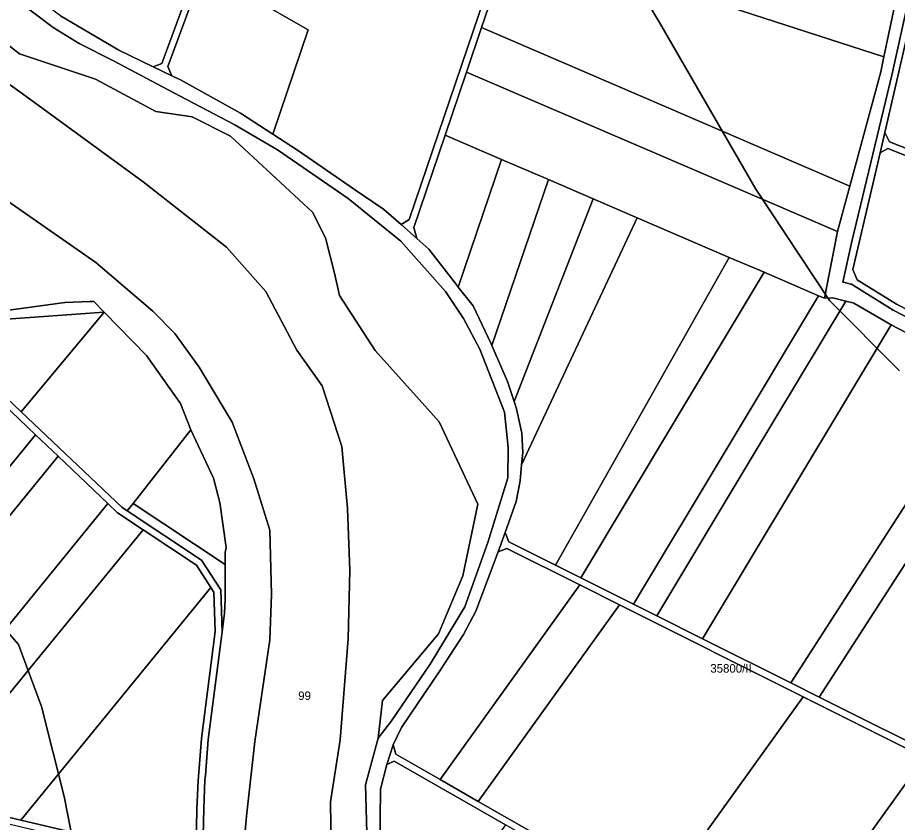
# Model space of a CAD drawing. Extents: x -545779 to -541342, y -1153413 to -1149956.
# Drawn here: x -542843 to -542328, y -1151005 to -1150533 of the extents above; entities that cross this region are included whole.
import ezdxf

# ---------------------------------------------------------------- set-up
doc = ezdxf.new("R2010")
doc.units = 0
for name, color, linetype in [('95560013', 7, 'Continuous'), ('95610013', 7, 'Continuous'), ('95620013', 7, 'Continuous'), ('95630013', 7, 'Continuous'), ('95640013', 7, 'Continuous'), ('95660013', 7, 'Continuous')]:
    doc.layers.add(name, color=color, linetype=linetype)

msp = doc.modelspace()

# ---------------------------------------------------------------- linework, layer by layer
at = {"layer": '95560013'}
for points in [[(-542330.19, -1150487.71), (-542329.65, -1150527.02), (-542335.84, -1150556.5), (-542444.5, -1150521.18), (-542553.15, -1150485.85), (-542525.28, -1150403.7), (-542332.68, -1150445.62)], [(-542645.66, -1150634.13), (-542678.6, -1150611.44), (-542693.55, -1150601.76), (-542672.83, -1150540.72), (-542734.13, -1150505.55), (-542702.1, -1150418.51), (-542538.9, -1150431.11), (-542576.35, -1150541.42), (-542613.8, -1150651.74), (-542618.41, -1150654.69), (-542628.79, -1150645.63)], [(-542763.51, -1150562.3), (-542783.62, -1150552.52), (-542817.82, -1150532.5), (-542849.86, -1150508.94), (-542861.66, -1150502.34), (-542839.07, -1150445.37), (-542737.65, -1150503.54), (-542758.53, -1150560.29)], [(-542337.68, -1150565.29), (-542355.74, -1150632.12), (-542463.52, -1150585.76), (-542571.31, -1150539.39), (-542553.15, -1150485.85), (-542444.5, -1150521.18), (-542335.84, -1150556.5)], [(-542238.79, -1150518.76), (-542265.23, -1150632.79), (-542332.56, -1150606.25), (-542335.38, -1150600.88), (-542318.46, -1150527.93), (-542319.28, -1150493.32)], [(-542747.63, -1150570.02), (-542752.7, -1150567.55), (-542754.92, -1150562.05), (-542734.13, -1150505.55), (-542672.83, -1150540.72), (-542693.55, -1150601.76), (-542712.51, -1150589.48)], [(-542471.54, -1150612.08), (-542580.12, -1150565.37), (-542571.31, -1150539.39), (-542463.52, -1150585.76), (-542355.74, -1150632.12), (-542362.95, -1150658.79)], [(-542580.12, -1150565.37), (-542471.54, -1150612.08), (-542362.95, -1150658.79), (-542363.21, -1150659.75), (-542370.7, -1150697.82), (-542374.07, -1150696.37), (-542405.95, -1150682.66), (-542426.33, -1150673.89), (-542480.19, -1150650.72), (-542505.95, -1150639.64), (-542532.27, -1150628.32), (-542559.66, -1150616.54), (-542592.68, -1150602.33)], [(-542586.51, -1150689.38), (-542602.24, -1150669.02), (-542609.26, -1150662.77), (-542610.97, -1150656.32), (-542592.68, -1150602.33), (-542559.66, -1150616.54), (-542585.01, -1150691.28)], [(-542303.72, -1150714.04), (-542305.3, -1150713.22), (-542328.41, -1150701.27), (-542351.47, -1150687.05), (-542353.96, -1150681.05), (-542338.1, -1150612.62), (-542333.47, -1150610.19), (-542284.15, -1150629.63)], [(-542532.27, -1150628.32), (-542565.25, -1150725.57), (-542565.68, -1150724.59), (-542576.23, -1150702.32), (-542585.01, -1150691.28), (-542559.66, -1150616.54)], [(-542505.95, -1150639.64), (-542552.24, -1150758.4), (-542556.14, -1150746.63), (-542565.25, -1150725.57), (-542532.27, -1150628.32)], [(-542547.18, -1150788.22), (-542547.73, -1150776.78), (-542550.87, -1150762.55), (-542552.24, -1150758.4), (-542505.95, -1150639.64), (-542480.19, -1150650.72), (-542547.89, -1150795.48)], [(-542551.16, -1150816.8), (-542548.81, -1150804.8), (-542547.89, -1150795.48), (-542480.19, -1150650.72), (-542426.33, -1150673.89), (-542477.22, -1150764.01), (-542528.11, -1150854.13), (-542555.31, -1150840.52), (-542557.56, -1150834.96)], [(-542426.33, -1150673.89), (-542405.95, -1150682.66), (-542459.52, -1150771.94), (-542513.29, -1150861.55), (-542528.11, -1150854.13), (-542477.22, -1150764.01)], [(-542428.26, -1150786.68), (-542482.44, -1150876.98), (-542513.29, -1150861.55), (-542459.52, -1150771.94), (-542405.95, -1150682.66), (-542374.07, -1150696.37)], [(-542374.07, -1150696.37), (-542370.7, -1150697.82), (-542365.74, -1150697.59), (-542358.22, -1150699.49), (-542413.51, -1150791.64), (-542468.81, -1150883.8), (-542482.44, -1150876.98), (-542428.26, -1150786.68)], [(-542413.51, -1150791.64), (-542358.22, -1150699.49), (-542354, -1150700.56), (-542353.42, -1150700.71), (-542331.67, -1150713.45), (-542386.81, -1150805.35), (-542441.95, -1150897.24), (-542468.81, -1150883.8)], [(-542274.43, -1150743.21), (-542332.4, -1150833.13), (-542390.37, -1150923.05), (-542441.95, -1150897.24), (-542386.81, -1150805.35), (-542331.67, -1150713.45)], [(-542332.4, -1150833.13), (-542274.43, -1150743.21), (-542257.9, -1150751.81), (-542315.79, -1150841.6), (-542373.68, -1150931.4), (-542390.37, -1150923.05)], [(-542257.9, -1150751.81), (-542196.89, -1150783.53), (-542172.78, -1150796.01), (-542235.1, -1150882.79), (-542297.41, -1150969.57), (-542373.68, -1150931.4), (-542315.79, -1150841.6)], [(-542856.45, -1150755.01), (-542832.51, -1150777.76), (-542910.52, -1150873.23), (-542988.53, -1150968.7), (-543024.19, -1150960.3), (-542940.33, -1150857.67)], [(-542819.24, -1150790.38), (-542894, -1150881.87), (-542968.76, -1150973.35), (-542988.53, -1150968.7), (-542910.52, -1150873.23), (-542832.51, -1150777.76)], [(-542925.32, -1150983.58), (-542968.76, -1150973.35), (-542894, -1150881.87), (-542819.24, -1150790.38), (-542790.1, -1150818.09), (-542857.71, -1150900.84)], [(-542784.49, -1150823.42), (-542769.44, -1150833.43), (-542833.46, -1150911.78), (-542897.48, -1150990.13), (-542925.32, -1150983.58), (-542857.71, -1150900.84), (-542790.1, -1150818.09)], [(-542729.75, -1150867.3), (-542840.99, -1151003.43), (-542897.48, -1150990.13), (-542833.46, -1150911.78), (-542769.44, -1150833.43), (-542738.27, -1150854.18)], [(-542595.71, -1150916.11), (-542581.96, -1150894.8), (-542574.79, -1150881.02), (-542561.62, -1150846.28), (-542556.63, -1150844.33), (-542513.84, -1150865.74), (-542595.66, -1150979.67), (-542621.45, -1150964.92), (-542623.17, -1150959.34), (-542618.19, -1150949.13)], [(-542595.66, -1150979.67), (-542513.84, -1150865.74), (-542490.6, -1150877.37), (-542573.26, -1150992.48)], [(-542729.75, -1150867.3), (-542728.03, -1150869.94), (-542727.2, -1150893.07), (-542735.35, -1150955.74), (-542737.3, -1150980.51), (-542737.99, -1150996.76), (-542738.48, -1151020.04), (-542738.32, -1151027.6), (-542840.99, -1151003.43)], [(-542383.03, -1150931.2), (-542312.07, -1150966.7), (-542401.24, -1151090.85), (-542469.6, -1151051.76)], [(-542623.4, -1151098.08), (-542630.67, -1151064.57), (-542630.81, -1151049.59), (-542629.35, -1151044.93), (-542629.55, -1151024.45), (-542630.99, -1151020.31), (-542630.5, -1150985.34), (-542626.89, -1150970.85), (-542622.45, -1150968.96), (-542557.39, -1151006.17)], [(-542401.24, -1151090.85), (-542312.07, -1150966.7), (-542234.43, -1151005.56), (-542326.42, -1151133.64)]]:
    msp.add_lwpolyline(points, close=True, dxfattribs=at)
at = {"layer": '95610013'}
for points in [[(-542852.21, -1150710.28), (-542792.22, -1150705.95), (-542840.86, -1150764.31), (-542879.48, -1150727.6), (-542863.52, -1150707.95)], [(-542792.22, -1150705.95), (-542767.48, -1150731.43), (-542747.62, -1150759.55), (-542741.51, -1150774.97), (-542775.27, -1150817.95), (-542778.77, -1150822.41), (-542781.98, -1150820.28), (-542840.86, -1150764.31)], [(-542573.26, -1150992.48), (-542490.6, -1150877.37), (-542383.03, -1150931.2), (-542469.6, -1151051.76)]]:
    msp.add_lwpolyline(points, close=True, dxfattribs=at)
at = {"layer": '95620013'}
for points in [[(-542724.58, -1150817.54), (-542720.95, -1150843.81), (-542721.4, -1150846.72), (-542721.41, -1150853.81), (-542775.27, -1150817.95), (-542741.51, -1150774.97), (-542732.72, -1150793.68), (-542728.24, -1150803.21)], [(-542778.77, -1150822.41), (-542775.27, -1150817.95), (-542721.41, -1150853.81), (-542721.43, -1150860.66), (-542721.46, -1150874.27), (-542721.75, -1150882.21), (-542723.19, -1150893.25), (-542724.07, -1150868.69), (-542735.37, -1150851.31)]]:
    msp.add_lwpolyline(points, close=True, dxfattribs=at)
at = {"layer": '95630013'}
for points in [[(-542274.43, -1150743.21), (-542331.67, -1150713.45), (-542353.42, -1150700.71), (-542354, -1150700.56), (-542358.22, -1150699.49), (-542365.74, -1150697.59), (-542370.7, -1150697.82), (-542363.21, -1150659.75), (-542362.95, -1150658.79), (-542355.74, -1150632.12), (-542337.68, -1150565.29), (-542335.84, -1150556.5), (-542329.65, -1150527.02)], [(-542322.47, -1150527.52), (-542331.21, -1150567.12), (-542354.69, -1150664.61), (-542359.8, -1150688.41), (-542359.5, -1150688.49), (-542355.18, -1150689.58), (-542354.84, -1150689.67), (-542330.38, -1150704.75), (-542192.55, -1150776.06)], [(-542853.27, -1150568.8), (-542840.3, -1150577.96), (-542769.53, -1150629.69), (-542720.62, -1150667.89), (-542697.73, -1150693.85), (-542679.4, -1150728.18), (-542664.57, -1150749.17), (-542653.18, -1150784.63), (-542649.87, -1150820.92), (-542648.38, -1150857.27), (-542649.36, -1150897.36), (-542654.05, -1150956.36), (-542659.77, -1150992.79), (-542659.3, -1151020.78)], [(-542711.12, -1151025.21), (-542708.98, -1151001.05), (-542704.01, -1150957.37), (-542695.25, -1150897.83), (-542694.4, -1150871.37), (-542695.3, -1150833.71), (-542704.75, -1150803.6), (-542717.27, -1150770.47), (-542736.65, -1150738.22), (-542750.99, -1150718.53), (-542763.83, -1150705.4), (-542797.14, -1150676.99), (-542877.1, -1150621.25)]]:
    msp.add_lwpolyline(points, dxfattribs=at)
at = {"layer": '95640013'}
msp.add_lwpolyline([(-542680.59, -1150348.45), (-542673.59, -1150329.44), (-542612.5, -1150163.4), (-542614.98, -1150158.86), (-542611.81, -1150160.9), (-542604.8, -1150165.43), (-542610.13, -1150168.54), (-542617.93, -1150189.75), (-542642.91, -1150257.63), (-542651.79, -1150281.78), (-542662.14, -1150309.9), (-542673.7, -1150341.32), (-542678.36, -1150353.99), (-542695.93, -1150401.74), (-542702.1, -1150418.51), (-542734.13, -1150505.55), (-542754.92, -1150562.05), (-542752.7, -1150567.55), (-542763.51, -1150562.3), (-542758.53, -1150560.29), (-542737.65, -1150503.54), (-542722.86, -1150463.35), (-542698.75, -1150397.83)], close=True, dxfattribs=at)
for points in [[(-542553.15, -1150485.85), (-542571.31, -1150539.39), (-542580.12, -1150565.37), (-542592.68, -1150602.33), (-542610.97, -1150656.32), (-542609.26, -1150662.77), (-542618.41, -1150654.69), (-542613.8, -1150651.74), (-542576.35, -1150541.42), (-542538.9, -1150431.11)], [(-542854.19, -1150515.06), (-542822.11, -1150539.26), (-542806.95, -1150548.7), (-542786.83, -1150558.73), (-542751.54, -1150577.56), (-542716.17, -1150596.02), (-542690.78, -1150610.95), (-542649.47, -1150639.4), (-542618.67, -1150664.43), (-542592.51, -1150693.89), (-542581.97, -1150709.69), (-542572.32, -1150727.63), (-542558.01, -1150764.47), (-542555.82, -1150785.27), (-542555.97, -1150802.94), (-542567.63, -1150840.97), (-542581.09, -1150878.47), (-542601.49, -1150912.16), (-542624.02, -1150945.26), (-542631.93, -1150955.49), (-542629.3, -1150933.48), (-542596.64, -1150894.43), (-542582.38, -1150860.37), (-542573.58, -1150818.49), (-542596.15, -1150770.14), (-542607.9, -1150757.1), (-542633.68, -1150728.52), (-542654.53, -1150696.16), (-542657.39, -1150683.24), (-542662.72, -1150662.44), (-542670.37, -1150647.36), (-542718.31, -1150602.84), (-542740.68, -1150591.53), (-542762.06, -1150588.54), (-542797.36, -1150569.62), (-542841.86, -1150554.66), (-542931.65, -1150484.68)], [(-542931.65, -1150484.68), (-542841.86, -1150554.66), (-542797.36, -1150569.62), (-542762.06, -1150588.54), (-542740.68, -1150591.53), (-542718.31, -1150602.84), (-542670.37, -1150647.36), (-542662.72, -1150662.44), (-542657.39, -1150683.24), (-542654.53, -1150696.16), (-542633.68, -1150728.52), (-542607.9, -1150757.1), (-542596.15, -1150770.14), (-542573.58, -1150818.49), (-542582.38, -1150860.37), (-542596.64, -1150894.43), (-542629.3, -1150933.48), (-542631.93, -1150955.49), (-542639.22, -1150982.71), (-542638.05, -1151024.8)], [(-542638.05, -1151024.8), (-542639.22, -1150982.71), (-542631.93, -1150955.49), (-542624.02, -1150945.26), (-542601.49, -1150912.16), (-542581.09, -1150878.47), (-542567.63, -1150840.97), (-542555.97, -1150802.94), (-542555.82, -1150785.27), (-542558.01, -1150764.47), (-542572.32, -1150727.63), (-542581.97, -1150709.69), (-542592.51, -1150693.89), (-542618.67, -1150664.43), (-542649.47, -1150639.4), (-542690.78, -1150610.95), (-542716.17, -1150596.02), (-542751.54, -1150577.56), (-542786.83, -1150558.73), (-542806.95, -1150548.7), (-542822.11, -1150539.26), (-542854.19, -1150515.06)], [(-542192.55, -1150776.06), (-542330.38, -1150704.75), (-542354.84, -1150689.67), (-542355.18, -1150689.58), (-542359.5, -1150688.49), (-542359.8, -1150688.41), (-542354.69, -1150664.61), (-542331.21, -1150567.12), (-542322.47, -1150527.52)], [(-542318.46, -1150527.93), (-542335.38, -1150600.88), (-542338.1, -1150612.62), (-542353.96, -1150681.05), (-542351.47, -1150687.05), (-542328.41, -1150701.27), (-542305.3, -1150713.22)], [(-542817.82, -1150532.5), (-542783.62, -1150552.52), (-542763.51, -1150562.3), (-542752.7, -1150567.55), (-542747.63, -1150570.02), (-542712.51, -1150589.48), (-542693.55, -1150601.76), (-542678.6, -1150611.44), (-542645.66, -1150634.13), (-542628.79, -1150645.63), (-542618.41, -1150654.69), (-542609.26, -1150662.77), (-542602.24, -1150669.02), (-542586.51, -1150689.38), (-542585.01, -1150691.28), (-542576.23, -1150702.32), (-542565.68, -1150724.59), (-542565.25, -1150725.57), (-542556.14, -1150746.63), (-542552.24, -1150758.4), (-542550.87, -1150762.55), (-542547.73, -1150776.78), (-542547.18, -1150788.22), (-542547.89, -1150795.48), (-542548.81, -1150804.8), (-542551.16, -1150816.8), (-542557.56, -1150834.96), (-542561.62, -1150846.28), (-542574.79, -1150881.02), (-542581.96, -1150894.8), (-542595.71, -1150916.11), (-542618.19, -1150949.13), (-542623.17, -1150959.34), (-542626.89, -1150970.85), (-542630.5, -1150985.34), (-542630.99, -1151020.31)], [(-542659.3, -1151020.78), (-542659.77, -1150992.79), (-542654.05, -1150956.36), (-542649.36, -1150897.36), (-542648.38, -1150857.27), (-542649.87, -1150820.92), (-542653.18, -1150784.63), (-542664.57, -1150749.17), (-542679.4, -1150728.18), (-542697.73, -1150693.85), (-542720.62, -1150667.89), (-542769.53, -1150629.69), (-542840.3, -1150577.96), (-542853.27, -1150568.8)], [(-542284.15, -1150629.63), (-542333.47, -1150610.19), (-542338.1, -1150612.62), (-542335.38, -1150600.88), (-542332.56, -1150606.25), (-542265.23, -1150632.79)], [(-542877.1, -1150621.25), (-542797.14, -1150676.99), (-542763.83, -1150705.4), (-542750.99, -1150718.53), (-542736.65, -1150738.22), (-542717.27, -1150770.47), (-542704.75, -1150803.6), (-542695.3, -1150833.71), (-542694.4, -1150871.37), (-542695.25, -1150897.83), (-542704.01, -1150957.37), (-542708.98, -1151001.05), (-542711.12, -1151025.21)], [(-542734.48, -1151020.04), (-542733.99, -1150996.89), (-542733.27, -1150979.77), (-542733.04, -1150977.32), (-542731.37, -1150956.16), (-542723.19, -1150893.25), (-542721.75, -1150882.21), (-542721.46, -1150874.27), (-542721.43, -1150860.66), (-542721.41, -1150853.81), (-542721.4, -1150846.72), (-542720.95, -1150843.81), (-542724.58, -1150817.54), (-542728.24, -1150803.21), (-542732.72, -1150793.68), (-542741.51, -1150774.97), (-542747.62, -1150759.55), (-542767.48, -1150731.43), (-542792.22, -1150705.95), (-542798.33, -1150699.67), (-542800.68, -1150699.77), (-542815.36, -1150700.43), (-542839.4, -1150703.66), (-542852.6, -1150705.43)], [(-542852.6, -1150705.43), (-542839.4, -1150703.66), (-542815.36, -1150700.43), (-542800.68, -1150699.77), (-542798.33, -1150699.67), (-542792.22, -1150705.95), (-542852.21, -1150710.28)], [(-542879.48, -1150727.6), (-542840.86, -1150764.31), (-542781.98, -1150820.28), (-542778.77, -1150822.41), (-542735.37, -1150851.31), (-542724.07, -1150868.69), (-542723.19, -1150893.25), (-542731.37, -1150956.16), (-542733.04, -1150977.32), (-542733.27, -1150979.77), (-542733.99, -1150996.89), (-542734.48, -1151020.04)], [(-542738.48, -1151020.04), (-542737.99, -1150996.76), (-542737.3, -1150980.51), (-542735.35, -1150955.74), (-542727.2, -1150893.07), (-542728.03, -1150869.94), (-542729.75, -1150867.3), (-542738.27, -1150854.18), (-542769.44, -1150833.43), (-542784.49, -1150823.42), (-542790.1, -1150818.09), (-542819.24, -1150790.38), (-542832.51, -1150777.76), (-542856.45, -1150755.01)], [(-542312.07, -1150966.7), (-542383.03, -1150931.2), (-542490.6, -1150877.37), (-542513.84, -1150865.74), (-542556.63, -1150844.33), (-542561.62, -1150846.28), (-542557.56, -1150834.96), (-542555.31, -1150840.52), (-542528.11, -1150854.13), (-542513.29, -1150861.55), (-542482.44, -1150876.98), (-542468.81, -1150883.8), (-542441.95, -1150897.24), (-542390.37, -1150923.05), (-542373.68, -1150931.4), (-542297.41, -1150969.57)], [(-542295.47, -1151155.96), (-542329.46, -1151136.52), (-542393.74, -1151099.75), (-542494.69, -1151042.03), (-542557.39, -1151006.17), (-542622.45, -1150968.96), (-542626.89, -1150970.85), (-542623.17, -1150959.34), (-542621.45, -1150964.92), (-542595.66, -1150979.67), (-542573.26, -1150992.48), (-542469.6, -1151051.76), (-542401.24, -1151090.85), (-542326.42, -1151133.64)], [(-542897.48, -1150990.13), (-542840.99, -1151003.43), (-542738.32, -1151027.6), (-542738.15, -1151035.84), (-542742.3, -1151030.77), (-542746.11, -1151029.88), (-542771.83, -1151023.82), (-542826.9, -1151010.86), (-542867.16, -1151001.38)]]:
    msp.add_lwpolyline(points, dxfattribs=at)
at = {"layer": '95660013'}
for points in [[(-542638.05, -1151024.8), (-542639.22, -1150982.71), (-542631.93, -1150955.49), (-542629.3, -1150933.48), (-542596.64, -1150894.43), (-542582.38, -1150860.37), (-542573.58, -1150818.49), (-542596.15, -1150770.14), (-542607.9, -1150757.1), (-542633.68, -1150728.52), (-542654.53, -1150696.16), (-542657.39, -1150683.24), (-542662.72, -1150662.44), (-542670.37, -1150647.36), (-542718.31, -1150602.84), (-542740.68, -1150591.53), (-542762.06, -1150588.54), (-542797.36, -1150569.62), (-542841.86, -1150554.66), (-542931.65, -1150484.68)], [(-542931.65, -1150484.68), (-542841.86, -1150554.66), (-542797.36, -1150569.62), (-542762.06, -1150588.54), (-542740.68, -1150591.53), (-542718.31, -1150602.84), (-542670.37, -1150647.36), (-542662.72, -1150662.44), (-542657.39, -1150683.24), (-542654.53, -1150696.16), (-542633.68, -1150728.52), (-542607.9, -1150757.1), (-542596.15, -1150770.14), (-542573.58, -1150818.49), (-542582.38, -1150860.37), (-542596.64, -1150894.43), (-542629.3, -1150933.48), (-542631.93, -1150955.49), (-542639.22, -1150982.71), (-542638.05, -1151024.8)], [(-542497.917, -1150484.75), (-542467.294, -1150536.427), (-542410.833, -1150634.038), (-542367.768, -1150699.113), (-542326.618, -1150740.263)], [(-542326.618, -1150740.263), (-542367.768, -1150699.113), (-542410.833, -1150634.038), (-542467.294, -1150536.427), (-542497.917, -1150484.75)], [(-542852.21, -1150710.28), (-542792.22, -1150705.95), (-542767.48, -1150731.43), (-542747.62, -1150759.55), (-542741.51, -1150774.97), (-542775.27, -1150817.95), (-542778.77, -1150822.41), (-542735.37, -1150851.31), (-542724.07, -1150868.69), (-542723.19, -1150893.25), (-542731.37, -1150956.16), (-542733.04, -1150977.32), (-542733.27, -1150979.77), (-542733.99, -1150996.89), (-542734.48, -1151020.04)], [(-542734.48, -1151020.04), (-542733.99, -1150996.89), (-542733.27, -1150979.77), (-542733.04, -1150977.32), (-542731.37, -1150956.16), (-542723.19, -1150893.25), (-542724.07, -1150868.69), (-542735.37, -1150851.31), (-542778.77, -1150822.41), (-542775.27, -1150817.95), (-542741.51, -1150774.97), (-542747.62, -1150759.55), (-542767.48, -1150731.43), (-542792.22, -1150705.95), (-542852.21, -1150710.28)], [(-542863.482, -1150876.631), (-542842.428, -1150900.556), (-542829.031, -1150936.921), (-542815.632, -1150989.554), (-542806.061, -1151038.36), (-542796.493, -1151068.026), (-542782.241, -1151127.272), (-542763.449, -1151180.515), (-542735.261, -1151235.845), (-542712.294, -1151261.945), (-542685.151, -1151282.824), (-542654.875, -1151299.528), (-542640.259, -1151304.748), (-542624.715, -1151307.858), (-542624.715, -1151307.858), (-542646.02, -1151328.82), (-542705.74, -1151387.58), (-542706.35, -1151388.18), (-542714.17, -1151395.87), (-542721.3, -1151402.89), (-542732.07, -1151413.48), (-542732.86, -1151414.83), (-542736.37, -1151418.2), (-542850.69, -1151527.98)], [(-542806.061, -1151038.36), (-542815.632, -1150989.554), (-542829.031, -1150936.921), (-542842.428, -1150900.556), (-542863.482, -1150876.631)]]:
    msp.add_lwpolyline(points, dxfattribs=at)

# ---------------------------------------------------------------- texts
for s, rotation, p in [('35800/II.', 0, (-542437.442, -1150917.094)), ('99', 360, (-542678.69, -1150933.115))]:
    msp.add_text(s, height=5, rotation=rotation, dxfattribs=at).set_placement(p)

doc.saveas('drawing.dxf')
